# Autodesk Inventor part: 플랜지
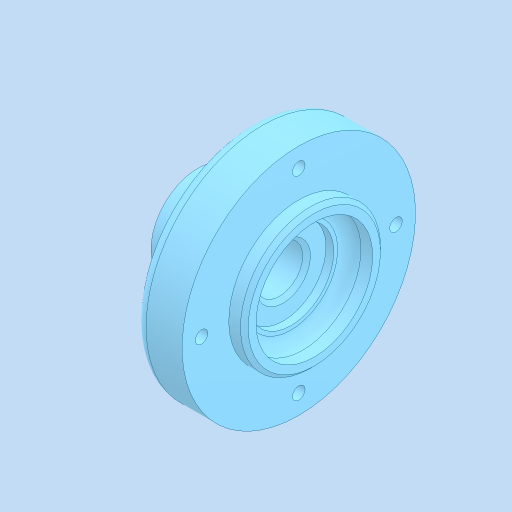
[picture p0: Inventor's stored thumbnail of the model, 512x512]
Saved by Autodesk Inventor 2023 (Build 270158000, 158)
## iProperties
Created: 2026-03
Part Number: 플랜지
Material: 강철, 연강
Document SubType Name: Modeling
Designer: home
Density: 7.85 g/cm^3
Appearance: 기본값
Author: jhkim
Sending System: Autodesk Inventor 2026
Preprocessor: ST-DEVELOPER v20.1
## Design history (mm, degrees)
feature "솔리드1"
node "솔리드2"
